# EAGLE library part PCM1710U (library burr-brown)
Dual Voltage Output CMOS Delta-Sigma DAC with On-Chip Digital Filter
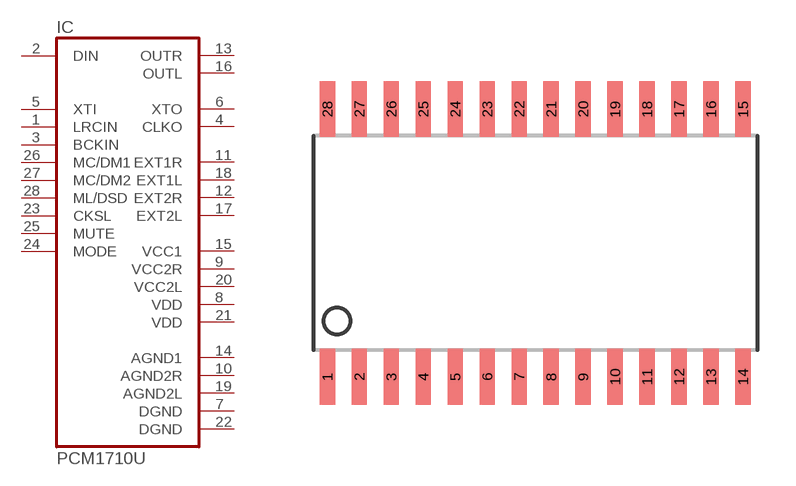
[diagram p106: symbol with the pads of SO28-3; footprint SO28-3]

Designator prefix IC

## PCM1710U (MF: TEXAS INSTRUMENT CONNECTORS; MPN: PCM1710U; OC_FARNELL: 1212857; OC_NEWARK: 75C5309)  [SO28-3]
1  LRCIN  in
2  DIN  in
3  BCKIN  in
4  CLKO  out
5  XTI  in
6  XTO  out
7  DGND  pwr
8  VDD  pwr
9  VCC2R  pwr
10  AGND2R  pwr
11  EXT1R  out
12  EXT2R  out
13  OUTR  out
14  AGND1  pwr
15  VCC1  pwr
16  OUTL  out
17  EXT2L  out
18  EXT1L  out
19  AGND2L  pwr
20  VCC2L  pwr
21  VDD  pwr
22  DGND  pwr
23  CKSL  in
24  MODE  in
25  MUTE  in
26  MC/DM1  in
27  MC/DM2  in
28  ML/DSD  in

## Footprint SO28-3 (pad centres in mm)
Small Outline Package
smd 0.61 x 2.21: 1 -8.255,-5.315; 2 -6.985,-5.315; 3 -5.715,-5.315; 4 -4.445,-5.315; 5 -3.175,-5.315; 6 -1.905,-5.315; 7 -0.635,-5.315; 8 0.635,-5.315; 9 1.905,-5.315; 10 3.175,-5.315; 11 4.445,-5.315; 12 5.715,-5.315; 13 6.985,-5.315; 14 8.255,-5.315; 15 8.255,5.315; 16 6.985,5.315; 17 5.715,5.315; 18 4.445,5.315; 19 3.175,5.315; 20 1.905,5.315; 21 0.635,5.315; 22 -0.635,5.315; 23 -1.905,5.315; 24 -3.175,5.315; 25 -4.445,5.315; 26 -5.715,5.315; 27 -6.985,5.315; 28 -8.255,5.315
